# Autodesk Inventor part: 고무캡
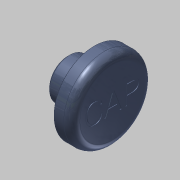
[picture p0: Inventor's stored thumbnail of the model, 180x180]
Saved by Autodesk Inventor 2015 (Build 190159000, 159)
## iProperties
Created: 2017-06
Part Number: 고무캡
Material: 고무
Document SubType Name: Modeling
Designer: mduedu
Density: 1 g/cm^3
Appearance: 고무 - 파란색 - 버전 1.1
Author: mduedu
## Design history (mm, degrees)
sketch "스케치1"
  geometry: L1 (0, 0)-(11, 0); L2 (11, 0)-(11, 10); L3 (11, 10)-(6.5, 10); L4 (0, 5)-(0, 0); L5 (0, 5)-(6, 5); L6 (6, 5)-(6, 9); L7 (6, 9)-(6.5, 9); L8 (6.5, 9)-(6.5, 10)
  constraints: 16 end point, 2 horizontal, 2 parallel, 2 perpendicular, 2 point on line, 1 vertical
  dimensions: "d0" = 20 diameter of L3 L1; "d2" = 10 diameter of L5 L1; "d6" = 5 distance between parallel lines of L2 L6; "d7" = 0.5 distance between parallel lines of L8 L6; "d8" = 18 diameter of L7 L1; "d9" = 6 distance between parallel lines of L6 L4
revolve "회전1" sketch "스케치1" stored, may be unused: angle "d10" = 90 deg
hole "구멍1" diameter "d22" = 7; stored, may be unused: countersink angle "d26" = 90 deg, drill point angle "d28" = 0 deg; dims "d23" = 6, "d24" = 4, "d25" = 2, "d27" = 6, "d32" = 10, "d33" = 10
chamfer "모따기1" distance "d13" = 0.5; stored, may be unused: second distance "d14" = 2, angle "d15" = 45 deg
fillet "모깎기3" dims "d29" = 1
fillet "모깎기1" dims "d16" = 0.1
fillet "모깎기2" dims "d17" = 2
sketch "스케치3"
  geometry: 2 further points
  constraints: 1 coincident, 1 other
feature "엠보싱1" sketch "스케치3" dims "d18" = 0.2, "d19" = 0
node "솔리드1"
